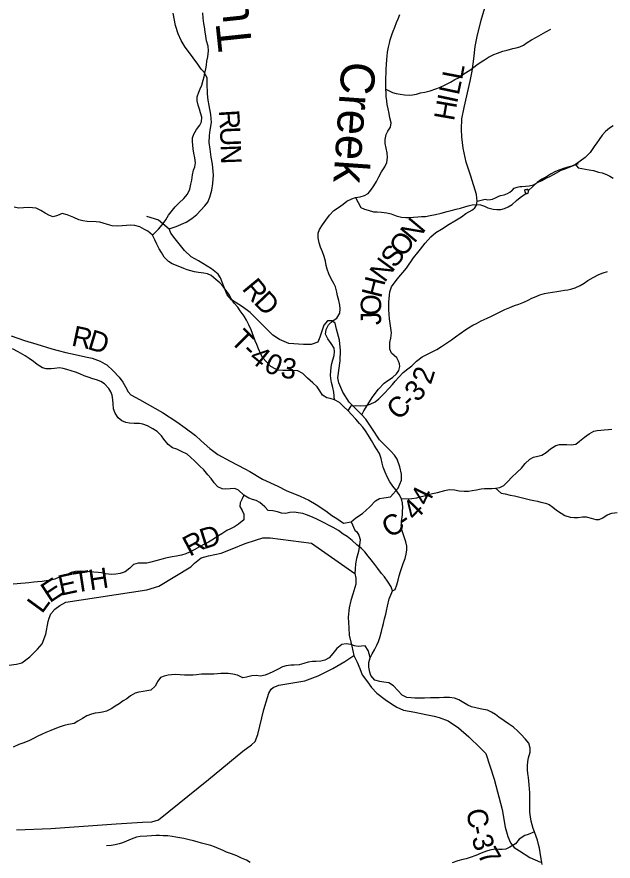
# Model space of a CAD drawing. Extents: x 1578669 to 1989827, y 208020 to 553079.
# Drawn here: x 1795443 to 1804212, y 411669 to 424095 of the extents above; entities that cross this region are included whole.
import ezdxf

# ---------------------------------------------------------------- set-up
doc = ezdxf.new("R2010")
doc.units = 0
for name, color, linetype in [('GM_X_County_Road', 7, 'Continuous'), ('GM_X_County_Road_Text', 7, 'Continuous'), ('GM_X_Major_River', 7, 'Continuous'), ('GM_X_Minor_Lake', 7, 'Continuous'), ('GM_X_Minor_River', 7, 'Continuous'), ('GM_X_Minor_River_Text', 7, 'Continuous'), ('GM_X_Township_Road', 7, 'Continuous'), ('GM_X_Township_Road_Text', 7, 'Continuous'), ('GM_X_Township_ROW', 7, 'Continuous')]:
    doc.layers.add(name, color=color, linetype=linetype)

msp = doc.modelspace()

# ---------------------------------------------------------------- linework, layer by layer
at = {"layer": 'GM_X_County_Road'}
for points in [[(1800515, 418239), (1800543, 418295), (1800602, 418389), (1800668, 418491), (1800763, 418615), (1800845, 418703), (1800897, 418741), (1800968, 418788), (1801028, 418842), (1801060, 418888), (1801076, 418948), (1801070, 418989), (1801054, 419029), (1801033, 419075), (1800951, 419143), (1800929, 419205), (1800927, 419304), (1800943, 419366), (1800954, 419444), (1800924, 419650), (1800913, 419787), (1800913, 419895), (1800925, 420001), (1800929, 420049), (1800954, 420123), (1801038, 420237), (1801173, 420399), (1801278, 420547), (1801341, 420628), (1801378, 420677), (1801445, 420765), (1801529, 420859), (1801605, 420921), (1801690, 420971), (1801802, 421045), (1801886, 421093), (1801981, 421150), (1802045, 421200), (1802145, 421256), (1802178, 421286), (1802200, 421324), (1802212, 421382), (1802204, 421482), (1802121, 421749), (1802051, 421956), (1802004, 422164), (1801989, 422331), (1801983, 422437), (1801989, 422597), (1802020, 422760), (1802111, 423150), (1802140, 423298), (1802163, 423477), (1802183, 423661), (1802210, 423807), (1802269, 424048), (1802370, 424380)], [(1795359, 419401), (1795552, 419332), (1795736, 419277), (1795958, 419208), (1796052, 419184), (1796160, 419154), (1796302, 419125), (1796452, 419091), (1796549, 419072), (1796665, 419028), (1796735, 418990), (1796763, 418974), (1796860, 418885), (1796946, 418793), (1797000, 418718), (1797040, 418652), (1797080, 418578), (1797118, 418534), (1797246, 418461), (1797584, 418272), (1797796, 418137), (1797918, 418048), (1798068, 417935), (1798154, 417853), (1798279, 417742), (1798399, 417652), (1798577, 417557), (1798793, 417444), (1798871, 417402), (1799057, 417293), (1799281, 417188), (1799401, 417126), (1799610, 417041), (1799738, 416982), (1799844, 416918), (1799984, 416823), (1800076, 416755), (1800146, 416713), (1800245, 416642), (1800360, 416663), (1800413, 416539), (1800441, 416517), (1800473, 416465), (1800489, 416401), (1800481, 416319), (1800465, 416227), (1800436, 416124), (1800424, 416046), (1800418, 415968), (1800411, 415904), (1800429, 415832), (1800427, 415744), (1800384, 415597), (1800354, 415503), (1800328, 415395), (1800313, 415259), (1800327, 415101), (1800328, 414994), (1800368, 414832), (1800396, 414696), (1800445, 414595), (1800485, 414503), (1800523, 414409), (1800597, 414306), (1800657, 414224), (1800736, 414139), (1800860, 414049), (1800952, 413982), (1801032, 413936), (1801128, 413892), (1801295, 413859), (1801455, 413825), (1801581, 413800), (1801655, 413784), (1801787, 413735), (1801937, 413631), (1802089, 413496), (1802263, 413333), (1802342, 413251), (1802464, 412875), (1802582, 412426), (1802622, 412168), (1802661, 412033), (1802703, 411939), (1802755, 411869), (1802833, 411818), (1802989, 411723), (1803143, 411651)], [(1800360, 416663), (1800427, 416720), (1800528, 416787), (1800633, 416885), (1800715, 416970), (1800778, 417005), (1800838, 417014), (1800936, 417030), (1801050, 417157), (1801098, 417274), (1801098, 417363), (1801076, 417470), (1801035, 417584), (1800997, 417644), (1800940, 417701), (1800848, 417796), (1800778, 417869), (1800674, 418027), (1800576, 418173), (1800515, 418239)]]:
    msp.add_lwpolyline(points, dxfattribs=at)
at = {"layer": 'GM_X_Major_River'}
for points in [[(1795623, 419065), (1795563, 419104), (1795459, 419164), (1795379, 419207)], [(1800833, 415164), (1800851, 415236), (1800868, 415302), (1800878, 415354), (1800891, 415422), (1800920, 415530), (1800948, 415596), (1800965, 415646), (1800945, 415708), (1800904, 415777), (1800850, 415851), (1800804, 415904), (1800751, 415978), (1800709, 416035), (1800654, 416105), (1800608, 416158), (1800562, 416220), (1800511, 416271), (1800443, 416325), (1800375, 416386), (1800301, 416445), (1800243, 416483), (1800172, 416534), (1800094, 416580), (1800028, 416613), (1799970, 416644), (1799902, 416676), (1799844, 416707), (1799766, 416739), (1799700, 416766), (1799646, 416784), (1799578, 416797), (1799520, 416803), (1799458, 416798), (1799400, 416786), (1799333, 416790), (1799277, 416811), (1799209, 416827), (1799137, 416828), (1799087, 416882), (1799018, 416949), (1798962, 416978), (1798906, 416992), (1798852, 417010), (1798782, 417057), (1798702, 417130), (1798650, 417154), (1798580, 417147), (1798510, 417145), (1798460, 417146), (1798396, 417180), (1798344, 417239), (1798301, 417301), (1798253, 417356), (1798191, 417426), (1798128, 417487), (1798062, 417556), (1797998, 417616), (1797946, 417657), (1797866, 417699), (1797797, 417730), (1797733, 417754), (1797667, 417799), (1797605, 417878), (1797567, 417930), (1797508, 417991), (1797442, 418033), (1797362, 418078), (1797296, 418102), (1797244, 418109), (1797168, 418111), (1797098, 418114), (1797044, 418126), (1796986, 418147), (1796934, 418193), (1796888, 418262), (1796863, 418326), (1796857, 418404), (1796854, 418459), (1796844, 418525), (1796826, 418575), (1796795, 418625), (1796733, 418692), (1796677, 418729), (1796613, 418751), (1796559, 418769), (1796489, 418792), (1796433, 418814), (1796367, 418839), (1796305, 418866), (1796243, 418884), (1796179, 418905), (1796123, 418921), (1796071, 418929), (1795995, 418920), (1795945, 418914), (1795875, 418913), (1795821, 418929), (1795741, 418980), (1795687, 419022), (1795623, 419065)], [(1803169, 411620), (1803160, 411680), (1803150, 411730), (1803139, 411796), (1803127, 411857), (1803116, 411915), (1803098, 411979), (1803080, 412032), (1803055, 412100), (1803037, 412150), (1803020, 412202), (1803008, 412259), (1802998, 412319), (1802989, 412391), (1802987, 412451), (1802988, 412555), (1802987, 412610), (1802985, 412674), (1802984, 412732), (1802978, 412792), (1802972, 412844), (1802967, 412900), (1802959, 412957), (1802954, 413013), (1802954, 413069), (1802957, 413133), (1802969, 413187), (1802992, 413271), (1802994, 413329), (1802971, 413404), (1802919, 413468), (1802858, 413531), (1802810, 413583), (1802748, 413642), (1802674, 413691), (1802608, 413731), (1802533, 413788), (1802481, 413826), (1802425, 413863), (1802363, 413891), (1802307, 413902), (1802257, 413910), (1802193, 413923), (1802129, 413941), (1802075, 413966), (1802017, 413996), (1801945, 414043), (1801877, 414069), (1801805, 414078), (1801723, 414076), (1801652, 414073), (1801584, 414071), (1801524, 414070), (1801436, 414066), (1801297, 414067), (1801243, 414072), (1801179, 414078), (1801111, 414111), (1801044, 414180), (1800980, 414250), (1800912, 414291), (1800838, 414305), (1800780, 414314), (1800706, 414334), (1800650, 414401), (1800633, 414451), (1800619, 414523), (1800620, 414594), (1800638, 414662), (1800669, 414718), (1800701, 414780), (1800736, 414845), (1800761, 414903), (1800781, 414959), (1800806, 415047), (1800818, 415110), (1800833, 415164)]]:
    msp.add_lwpolyline(points, dxfattribs=at)
at = {"layer": 'GM_X_Minor_Lake'}
for points in [[(1802957, 421553), (1802945, 421555), (1802931, 421552), (1802915, 421548), (1802907, 421540), (1802915, 421518), (1802929, 421498), (1802947, 421494), (1802961, 421501), (1802969, 421525), (1802969, 421541)], [(1802969, 421541), (1802957, 421553)]]:
    msp.add_lwpolyline(points, dxfattribs=at)
at = {"layer": 'GM_X_Minor_River'}
for points in [[(1797436, 420882), (1797526, 420971), (1797579, 421036), (1797631, 421109), (1797674, 421175), (1797732, 421248), (1797772, 421298), (1797829, 421359), (1797897, 421424), (1797950, 421486), (1797986, 421561), (1798003, 421633), (1798017, 421694), (1798026, 421772), (1798042, 421838), (1798059, 421890), (1798069, 421947), (1798060, 422023), (1798047, 422087), (1798037, 422151), (1798028, 422205), (1798026, 422263), (1798027, 422313), (1798043, 422369), (1798086, 422436), (1798132, 422500), (1798156, 422551), (1798161, 422619), (1798144, 422681), (1798128, 422735), (1798109, 422797), (1798093, 422861), (1798094, 422917), (1798118, 422985), (1798139, 423036), (1798163, 423092), (1798184, 423162), (1798198, 423213), (1798208, 423265), (1798221, 423331), (1798229, 423385), (1798238, 423444), (1798250, 423506), (1798263, 423598), (1798254, 423666), (1798233, 423744), (1798219, 423810), (1798210, 423874), (1798200, 423948), (1798193, 424000), (1798184, 424076), (1798176, 424154)], [(1800114, 418458), (1800103, 418573), (1800087, 418639), (1800068, 418713), (1800061, 418771), (1800055, 418823), (1800059, 418877), (1800066, 418939), (1800076, 418993), (1800089, 419048), (1800107, 419112), (1800114, 419168), (1800108, 419218), (1800063, 419288), (1800016, 419356), (1799980, 419423), (1799989, 419492), (1800028, 419562), (1800094, 419625), (1800146, 419663), (1800193, 419732), (1800199, 419800), (1800192, 419852), (1800178, 419922), (1800159, 419988), (1800147, 420044), (1800128, 420120), (1800105, 420172), (1800067, 420242), (1800032, 420312), (1800007, 420382), (1799993, 420436), (1799980, 420498), (1799964, 420566), (1799937, 420638), (1799908, 420707), (1799888, 420771), (1799873, 420843), (1799876, 420914), (1799892, 420964), (1799937, 421036), (1799985, 421105), (1800040, 421176), (1800106, 421243), (1800174, 421291), (1800240, 421340), (1800297, 421381), (1800369, 421417), (1800421, 421436), (1800489, 421449), (1800555, 421467), (1800607, 421494), (1800649, 421546), (1800692, 421609), (1800734, 421674), (1800765, 421740), (1800805, 421813), (1800856, 421887), (1800886, 421952), (1800895, 422026), (1800889, 422096), (1800859, 422232), (1800857, 422290), (1800872, 422362), (1800900, 422415), (1800939, 422473), (1800945, 422538), (1800928, 422610), (1800916, 422674), (1800901, 422742), (1800890, 422808), (1800882, 422862), (1800875, 422922), (1800873, 422978), (1800870, 423032), (1800868, 423092), (1800869, 423146), (1800871, 423202), (1800872, 423260), (1800874, 423327), (1800879, 423393), (1800885, 423467), (1800888, 423517), (1800894, 423575), (1800907, 423652), (1800921, 423708), (1800934, 423758), (1800958, 423832), (1800977, 423883), (1801001, 423945), (1801028, 424012), (1801050, 424066), (1801075, 424132)], [(1800870, 423032), (1800969, 422983), (1801019, 422967), (1801078, 422958), (1801142, 422950), (1801210, 422945), (1801260, 422947), (1801322, 422958), (1801380, 422975), (1801442, 422989), (1801520, 423008), (1801602, 423037), (1801656, 423057), (1801744, 423094), (1801818, 423135), (1801882, 423172), (1801936, 423200), (1802001, 423245), (1802121, 423323), (1802205, 423388), (1802269, 423432), (1802322, 423465), (1802378, 423501), (1802456, 423540), (1802512, 423563), (1802590, 423590), (1802652, 423606), (1802736, 423629), (1802786, 423640), (1802838, 423656), (1802892, 423681), (1802948, 423717), (1803012, 423758), (1803087, 423799), (1803153, 423838), (1803223, 423876), (1803297, 423917)], [(1804212, 422491), (1804158, 422456), (1804102, 422408), (1804053, 422353), (1804009, 422292), (1803973, 422240), (1803934, 422186), (1803872, 422101), (1803801, 422028), (1803729, 421971), (1803657, 421922), (1803603, 421900), (1803545, 421881), (1803481, 421862), (1803429, 421844), (1803365, 421819), (1803290, 421778), (1803234, 421742), (1803162, 421705), (1803094, 421656), (1802969, 421541)], [(1803657, 421922), (1803700, 421873), (1803750, 421865), (1803806, 421856), (1803858, 421846), (1803925, 421833), (1803999, 421811), (1804053, 421800), (1804112, 421776), (1804164, 421749), (1804214, 421721)], [(1800421, 421436), (1800503, 421288), (1800555, 421263), (1800611, 421249), (1800686, 421228), (1800740, 421227), (1800806, 421221), (1800884, 421212), (1800947, 421195), (1801023, 421169), (1801097, 421148), (1801162, 421140), (1801216, 421143), (1801276, 421146), (1801340, 421152), (1801392, 421155), (1801450, 421159), (1801522, 421170), (1801600, 421185), (1801682, 421204), (1801770, 421231), (1801830, 421243), (1801902, 421264), (1801965, 421279), (1802031, 421297), (1802082, 421316), (1802141, 421328), (1802203, 421335), (1802261, 421327), (1802321, 421308), (1802371, 421284), (1802448, 421265), (1802502, 421262), (1802558, 421262), (1802612, 421273), (1802670, 421299), (1802726, 421334), (1802790, 421391), (1802843, 421437), (1802929, 421498)], [(1797317, 420967), (1797251, 421003), (1797176, 421024), (1797110, 421031), (1797054, 421027), (1796990, 421020), (1796920, 421013), (1796846, 421021), (1796777, 421040), (1796713, 421060), (1796661, 421073), (1796610, 421081), (1796478, 421083), (1796410, 421093), (1796354, 421110), (1796281, 421140), (1796231, 421161), (1796181, 421181), (1796108, 421200), (1796042, 421173), (1795974, 421151), (1795924, 421170), (1795859, 421206), (1795795, 421245), (1795727, 421279), (1795674, 421286), (1795606, 421291), (1795540, 421285), (1795466, 421280), (1795402, 421294)], [(1800965, 415646), (1801007, 415669), (1801032, 415737), (1801050, 415802), (1801067, 415870), (1801085, 415930), (1801106, 415990), (1801126, 416049), (1801153, 416121), (1801169, 416186), (1801176, 416250), (1801176, 416304), (1801161, 416368), (1801140, 416442), (1801116, 416514), (1801101, 416566), (1801099, 416618), (1801100, 416668), (1801112, 416768), (1801115, 416818), (1801117, 416875), (1801114, 416935), (1801100, 417001), (1801067, 417064), (1801018, 417132), (1800974, 417188), (1800927, 417250), (1800892, 417313), (1800859, 417393), (1800831, 417465), (1800816, 417527), (1800802, 417595), (1800775, 417667), (1800732, 417735), (1800698, 417793), (1800657, 417860), (1800616, 417932), (1800569, 418002), (1800529, 418054), (1800482, 418109), (1800426, 418175), (1800365, 418242), (1800314, 418296), (1800247, 418362), (1800185, 418417), (1800114, 418458), (1800050, 418476), (1800000, 418489), (1799939, 418529), (1799897, 418593), (1799858, 418652), (1799793, 418710), (1799716, 418777), (1799646, 418845), (1799573, 418884), (1799497, 418889), (1799425, 418891), (1799355, 418888), (1799292, 418894), (1799240, 418913), (1799176, 418949), (1799107, 419024), (1799062, 419078), (1799030, 419132), (1798997, 419207), (1798972, 419275), (1798948, 419329), (1798927, 419381), (1798907, 419437), (1798888, 419491), (1798855, 419563), (1798821, 419633), (1798786, 419690), (1798727, 419768), (1798691, 419822), (1798640, 419883), (1798600, 419939), (1798569, 419997), (1798532, 420053), (1798476, 420128), (1798429, 420180), (1798370, 420230), (1798302, 420287), (1798245, 420315), (1798191, 420322), (1798113, 420331), (1798057, 420341), (1798002, 420356), (1797946, 420372), (1797896, 420393), (1797837, 420415), (1797725, 420462), (1797670, 420494), (1797608, 420559), (1797567, 420627), (1797536, 420681), (1797502, 420750), (1797471, 420814), (1797436, 420882), (1797370, 420942), (1797317, 420967)], [(1800314, 418296), (1800360, 418369), (1800428, 418373), (1800500, 418372), (1800578, 418377), (1800640, 418393), (1800712, 418428), (1800768, 418473), (1800845, 418552), (1800919, 418631), (1800965, 418683), (1801006, 418734), (1801062, 418792), (1801123, 418861), (1801191, 418914), (1801249, 418958), (1801322, 419027), (1801402, 419092), (1801482, 419133), (1801558, 419168), (1801618, 419201), (1801688, 419243), (1801759, 419294), (1801833, 419343), (1801895, 419388), (1801975, 419443), (1802030, 419483), (1802086, 419516), (1802148, 419556), (1802200, 419583), (1802272, 419622), (1802358, 419661), (1802424, 419689), (1802483, 419718), (1802541, 419747), (1802621, 419786), (1802693, 419816), (1802761, 419845), (1802825, 419868), (1802897, 419896), (1802961, 419927), (1803017, 419954), (1803079, 419980), (1803135, 420003), (1803201, 420024), (1803255, 420034), (1803319, 420045), (1803385, 420053), (1803443, 420062), (1803497, 420071), (1803547, 420079), (1803603, 420090), (1803655, 420106), (1803727, 420143), (1803785, 420178), (1803841, 420214), (1803920, 420261), (1804004, 420304), (1804064, 420329), (1804130, 420347)], [(1801100, 417001), (1801250, 417006), (1801324, 417017), (1801376, 417029), (1801454, 417052), (1801510, 417069), (1801580, 417085), (1801630, 417096), (1801684, 417111), (1801736, 417125), (1801800, 417140), (1801880, 417136), (1801949, 417121), (1802023, 417114), (1802085, 417112), (1802141, 417123), (1802203, 417136), (1802269, 417146), (1802321, 417151), (1802377, 417151), (1802428, 417154), (1802484, 417158), (1802548, 417169), (1802604, 417198), (1802661, 417256), (1802721, 417319), (1802798, 417390), (1802862, 417453), (1802920, 417519), (1802987, 417586), (1803041, 417615), (1803105, 417629), (1803165, 417646), (1803229, 417685), (1803293, 417739), (1803369, 417784), (1803423, 417799), (1803477, 417801), (1803529, 417800), (1803593, 417794), (1803663, 417805), (1803717, 417850), (1803791, 417909), (1803858, 417959), (1803928, 417998), (1803978, 418009), (1804030, 418011), (1804082, 418018), (1804142, 418020), (1804195, 418025)], [(1798782, 417057), (1798757, 417002), (1798726, 416940), (1798722, 416890), (1798755, 416830), (1798782, 416774), (1798778, 416690), (1798703, 416629), (1798645, 416590), (1798583, 416562), (1798529, 416533), (1798457, 416488), (1798399, 416452), (1798332, 416407), (1798262, 416364), (1798200, 416333), (1798128, 416295), (1798048, 416252), (1797980, 416215), (1797926, 416190), (1797862, 416174), (1797792, 416159), (1797728, 416148), (1797678, 416140), (1797628, 416127), (1797558, 416109), (1797486, 416088), (1797412, 416069), (1797354, 416055), (1797292, 416054), (1797228, 416055), (1797160, 416035), (1797102, 415980), (1797036, 415927), (1796962, 415904), (1796898, 415892), (1796834, 415889), (1796748, 415898), (1796688, 415910), (1796638, 415917), (1796575, 415923), (1796513, 415926), (1796443, 415932), (1796371, 415935), (1796305, 415934), (1796242, 415918), (1796183, 415889), (1796113, 415866), (1796055, 415842), (1795999, 415821), (1795941, 415804), (1795873, 415792), (1795813, 415785), (1795744, 415779), (1795690, 415774), (1795618, 415767), (1795564, 415761), (1795500, 415754), (1795448, 415748), (1795386, 415747)], [(1802484, 417158), (1802563, 417087), (1802625, 417076), (1802697, 417054), (1802761, 417043), (1802820, 417033), (1802878, 417016), (1802940, 417000), (1802995, 416987), (1803047, 416975), (1803101, 416966), (1803151, 416954), (1803217, 416939), (1803272, 416917), (1803326, 416880), (1803377, 416836), (1803449, 416789), (1803504, 416757), (1803580, 416732), (1803638, 416724), (1803699, 416727), (1803761, 416736), (1803817, 416736), (1803889, 416719), (1803958, 416698), (1804008, 416696), (1804062, 416721), (1804125, 416767), (1804193, 416792), (1804269, 416801)], [(1800638, 414662), (1800628, 414707), (1800610, 414771), (1800567, 414835), (1800513, 414834), (1800461, 414828), (1800409, 414839), (1800352, 414859), (1800284, 414868), (1800224, 414855), (1800150, 414799), (1800091, 414726), (1800035, 414661), (1799973, 414625), (1799911, 414612), (1799841, 414609), (1799791, 414607), (1799725, 414598), (1799665, 414575), (1799595, 414559), (1799523, 414554), (1799473, 414554), (1799405, 414545), (1799349, 414526), (1799283, 414492), (1799209, 414457), (1799155, 414432), (1799095, 414404), (1799025, 414389), (1798961, 414402), (1798897, 414396), (1798821, 414377), (1798764, 414368), (1798688, 414404), (1798620, 414421), (1798551, 414428), (1798501, 414432), (1798443, 414429), (1798391, 414427), (1798339, 414422), (1798221, 414421), (1798160, 414419), (1798084, 414410), (1798034, 414407), (1797978, 414407), (1797910, 414408), (1797842, 414412), (1797778, 414415), (1797717, 414410), (1797665, 414404), (1797609, 414393), (1797557, 414371), (1797516, 414318), (1797478, 414246), (1797411, 414187), (1797353, 414174), (1797300, 414164), (1797234, 414153), (1797184, 414139), (1797115, 414102), (1797059, 414059), (1797005, 414027), (1796947, 413986), (1796889, 413949), (1796837, 413917), (1796760, 413876), (1796704, 413863), (1796644, 413851), (1796593, 413844), (1796541, 413834), (1796469, 413807), (1796408, 413766), (1796340, 413728), (1796284, 413695), (1796204, 413678), (1796140, 413666), (1796064, 413641), (1796000, 413616), (1795940, 413590), (1795870, 413561), (1795802, 413530), (1795750, 413506), (1795688, 413473), (1795618, 413440), (1795529, 413403), (1795469, 413383), (1795387, 413348)], [(1803055, 412100), (1802963, 412060), (1802913, 412045), (1802830, 411992), (1802774, 411925), (1802694, 411873), (1802632, 411846), (1802582, 411839), (1802532, 411841), (1802478, 411842), (1802400, 411828), (1802350, 411815), (1802270, 411786), (1802192, 411751), (1802108, 411721), (1802052, 411702), (1802002, 411692), (1801930, 411671), (1801846, 411642)], [(1798874, 411649), (1798818, 411683), (1798748, 411712), (1798677, 411744), (1798599, 411775), (1798526, 411802), (1798474, 411826), (1798349, 411877), (1798295, 411896), (1798218, 411916), (1798156, 411933), (1798096, 411953), (1798039, 411968), (1797975, 411983), (1797897, 411999), (1797841, 412010), (1797778, 412022), (1797724, 412031), (1797662, 412039), (1797594, 412042), (1797542, 412045), (1797491, 412045), (1797421, 412042), (1797353, 412038), (1797257, 412029), (1797201, 412020), (1797121, 411991), (1797055, 411961), (1796997, 411936), (1796945, 411921), (1796887, 411909), (1796827, 411900), (1796761, 411892)]]:
    msp.add_lwpolyline(points, dxfattribs=at)
at = {"layer": 'GM_X_Township_Road'}
for points in [[(1800515, 418239), (1800329, 418423), (1800234, 418569), (1800177, 418708), (1800164, 418784), (1800196, 419031), (1800202, 419183), (1800189, 419335), (1800145, 419499), (1800126, 419588), (1800075, 419620), (1800012, 419620), (1799955, 419556), (1799898, 419379), (1799867, 419309), (1799772, 419271), (1799658, 419271), (1799442, 419290), (1799303, 419347), (1799208, 419411), (1799094, 419525), (1798873, 419746), (1798759, 419828), (1798600, 419930), (1798537, 420006), (1798486, 420129), (1798439, 420253), (1798404, 420310), (1798306, 420389), (1798116, 420503), (1798008, 420563), (1797910, 420655), (1797771, 420826), (1797705, 420911), (1797682, 420978), (1797787, 421009), (1797933, 421072), (1798014, 421128), (1798088, 421188), (1798146, 421248), (1798207, 421312), (1798249, 421370), (1798281, 421442), (1798309, 421544), (1798326, 421642), (1798332, 421765), (1798319, 421925), (1798301, 422031), (1798283, 422150), (1798270, 422248), (1798274, 422348), (1798284, 422428), (1798307, 422540), (1798297, 422657), (1798269, 422791), (1798254, 422871), (1798248, 422961), (1798240, 423122), (1798241, 423196), (1798191, 423286), (1798155, 423328), (1798105, 423397), (1798037, 423493), (1797965, 423584), (1797917, 423648), (1797860, 423748), (1797814, 423847), (1797776, 423969), (1797743, 424151)], [(1802212, 421382), (1802328, 421410), (1802370, 421404), (1802408, 421408), (1802440, 421414), (1802481, 421430), (1802523, 421451), (1802557, 421465), (1802609, 421475), (1802659, 421495), (1802693, 421513), (1802717, 421534), (1802719, 421535)], [(1797349, 421163), (1797527, 421106), (1797682, 420978)], [(1795985, 415360), (1796002, 415378), (1796072, 415430), (1796160, 415482), (1797355, 415663), (1797530, 415714), (1798003, 415999), (1798056, 416053), (1798106, 416095), (1798152, 416131), (1798262, 416161), (1798449, 416201), (1798609, 416264), (1798800, 416342), (1798950, 416395), (1799061, 416427), (1799169, 416429), (1799776, 416351), (1800411, 415904)], [(1792611, 414187), (1792748, 414174), (1793597, 414151), (1793892, 414134), (1794008, 414142), (1794107, 414177), (1794458, 414407), (1794631, 414527), (1794683, 414544), (1795200, 414549), (1795324, 414553), (1795436, 414568), (1795515, 414588), (1795635, 414674), (1795748, 414786), (1795816, 414866), (1795868, 415008), (1795901, 415194), (1795917, 415246), (1795940, 415310), (1795985, 415359), (1795985, 415360)], [(1795439, 412131), (1795940, 412148), (1796903, 412215), (1797290, 412242), (1797427, 412245), (1797525, 412275), (1798262, 412870), (1798766, 413287), (1798891, 413381), (1798945, 413431), (1798985, 413531), (1799073, 413902), (1799129, 414076), (1799150, 414140), (1799184, 414200), (1799210, 414226), (1799296, 414256), (1799677, 414321), (1799874, 414394), (1800090, 414504), (1800265, 414606), (1800396, 414696)]]:
    msp.add_lwpolyline(points, dxfattribs=at)
at = {"layer": 'GM_X_Township_ROW'}
msp.add_lwpolyline([(1802719, 421535), (1802725, 421541), (1802756, 421573), (1802800, 421589), (1802838, 421597), (1802870, 421601), (1802922, 421605), (1802976, 421610), (1803040, 421622), (1803108, 421662), (1803165, 421688), (1803223, 421722), (1803283, 421746), (1803333, 421774), (1803377, 421798), (1803446, 421839), (1803494, 421853), (1803704, 421937)], dxfattribs=at)

# ---------------------------------------------------------------- texts
at = {"layer": 'GM_X_County_Road_Text'}
for s, rotation, p in [('L', 79.1742, (1801989, 423158)), ('L', 78.0243, (1801941, 422932)), ('I', 78.0012, (1801916, 422811)), ('H', 80.1897, (1801871, 422554)), ('N', 50.0475, (1801287, 420752)), ('O', 52.4496, (1801128, 420545)), ('S', 52.5172, (1801005, 420384)), ('N', 53.8208, (1800851, 420173)), ('H', 75.7597, (1800798, 419944)), ('O', 89.3552, (1800798, 419699)), ('J', 92.2546, (1800803, 419562)), ('R', 348.1282, (1796233, 419260)), ('D', 343.2425, (1796467, 419211)), ('2', 72.1892, (1801530, 418672)), ('3', 47.0333, (1801332, 418413)), ('C', 43.8933, (1801054, 418144)), ('-', 44.3329, (1801233, 418316)), ('4', 63.9992, (1801487, 416883)), ('4', 45.4771, (1801297, 416665)), ('C', 31.7001, (1800925, 416416)), ('-', 34.9449, (1801150, 416556)), ('C', 279.1126, (1802052, 412419)), ('-', 280.5471, (1802093, 412168)), ('3', 287.5196, (1802125, 412008)), ('7', 299.7714, (1802208, 411768))]:
    msp.add_text(s, height=300, rotation=rotation, dxfattribs=at).set_placement(p)
at = {"layer": 'GM_X_Minor_River_Text'}
for s, rotation, p in [('Turkey', 95.9992, (1798907, 423617)), ('Creek', 265.9801, (1800222, 423447))]:
    msp.add_text(s, height=500, rotation=rotation, dxfattribs=at).set_placement(p)
at = {"layer": 'GM_X_Township_Road_Text'}
for s, rotation, p in [('R', 273.6048, (1798412, 422719)), ('U', 272.2336, (1798428, 422475)), ('N', 272.0769, (1798438, 422211)), ('R', 309.6632, (1798743, 420090)), ('D', 313.607, (1798915, 419884)), ('T', 315.1667, (1798569, 419317)), ('-', 315.902, (1798731, 419156)), ('4', 320.7291, (1798840, 419052)), ('0', 336.4768, (1799060, 418888)), ('3', 351.2992, (1799310, 418791)), ('D', 17.4477, (1798189, 416257)), ('R', 27.8236, (1797984, 416147)), ('T', 8.7726, (1796300, 415620)), ('H', 8.6814, (1796521, 415654)), ('E', 33.192, (1795924, 415462)), ('E', 12.2294, (1796085, 415573)), ('L', 53.857, (1795812, 415300))]:
    msp.add_text(s, height=300, rotation=rotation, dxfattribs=at).set_placement(p)

doc.saveas('drawing.dxf')
